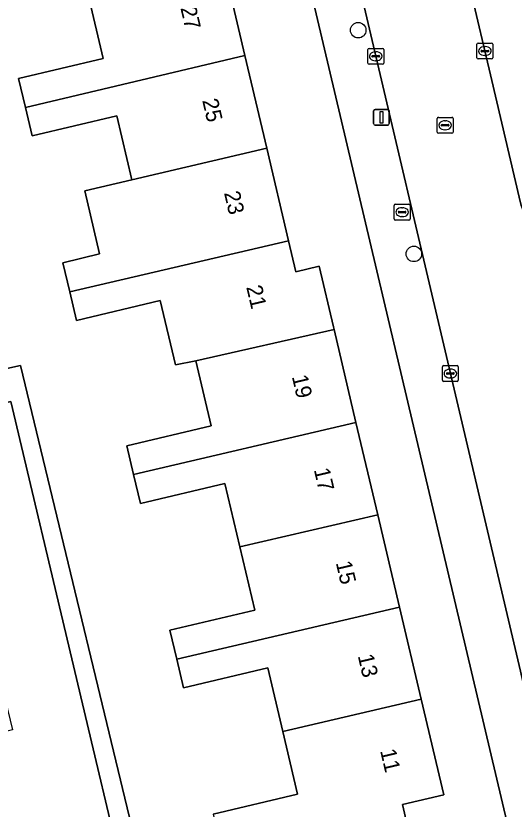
# Model space of a CAD drawing. Extents: x 158031 to 159244, y 380104 to 381214.
# Drawn here: x 158568.4 to 158599.9, y 380796.3 to 380846.4 of the extents above; entities that cross this region are included whole.
import ezdxf

# ---------------------------------------------------------------- set-up
doc = ezdxf.new("R2010")
doc.units = 0
for name, color, linetype in [('IMGEO_Boom', 7, 'Continuous'), ('IMGEO_Brandkraan', 7, 'Continuous'), ('IMGEO_Erf', 7, 'Continuous'), ('IMGEO_Kolk', 7, 'Continuous'), ('IMGEO_Lichtmast', 7, 'Continuous'), ('IMGEO_Pand', 7, 'Continuous'), ('IMGEO_Pand_nummerreeks', 7, 'Continuous'), ('IMGEO_Rijbaan_lokaal_open', 7, 'Continuous'), ('IMGEO_Rioolput', 7, 'Continuous'), ('IMGEO_Voetpad_open', 7, 'Continuous')]:
    doc.layers.add(name, color=color, linetype=linetype)

msp = doc.modelspace()

# ---------------------------------------------------------------- linework, layer by layer
at = {"layer": 'IMGEO_Boom'}
for centre in [(158590.04, 380845.479), (158593.559, 380831.355)]:
    msp.add_circle(centre, 0.489, dxfattribs=at)
at = {"layer": 'IMGEO_Brandkraan'}
for p, q in [((158592.316, 380833.564), (158592.316, 380834.416)), ((158592.391, 380834.49), (158593.243, 380834.49)), ((158592.804, 380834.27), (158592.829, 380834.27)), ((158593.317, 380834.416), (158593.317, 380833.564)), ((158592.575, 380833.984), (158592.575, 380833.996)), ((158593.013, 380833.947), (158592.615, 380833.947)), ((158592.618, 380834.033), (158593.016, 380834.033)), ((158592.827, 380833.71), (158592.802, 380833.71)), ((158593.059, 380833.996), (158593.059, 380833.984)), ((158593.243, 380833.49), (158592.391, 380833.49))]:
    msp.add_line(p, q, dxfattribs=at)
for points in [[(158592.316, 380833.564), (158592.316, 380834.416)], [(158592.391, 380834.49), (158593.243, 380834.49)], [(158593.317, 380834.416), (158593.317, 380833.564)], [(158593.243, 380833.49), (158592.391, 380833.49)]]:
    msp.add_lwpolyline(points, dxfattribs=at)
for centre, radius, start, end in [((158592.393, 380834.414), 0.0765, 91.552, 178.448), ((158592.393, 380834.414), 0.0765, 91.552, 178.448), ((158593.241, 380834.414), 0.0765, 1.552, 88.448), ((158593.241, 380834.414), 0.0765, 1.552, 88.448), ((158592.615, 380833.993), 0.0403, 85.8775, 175.7526), ((158592.612, 380833.983), 0.0366, 178.938, 274.7102), ((158593.016, 380833.99), 0.043, 264.8664, 352.4533), ((158593.02, 380833.995), 0.0386, 1.7309, 96.639), ((158592.393, 380833.566), 0.0765, 181.552, 268.448), ((158592.393, 380833.566), 0.0765, 181.552, 268.448), ((158593.241, 380833.566), 0.0765, 271.552, 358.448), ((158593.241, 380833.566), 0.0765, 271.552, 358.448)]:
    msp.add_arc(centre, radius, start, end, dxfattribs=at)
for centre, major_axis, ratio, start_param, end_param in [((158592.803, 380833.99), (-0.387, 0.002), 0.722429, 4.712389, 7.853982), ((158592.828, 380833.99), (-0.39, 0.002), 0.717154, 1.570796, 4.712389)]:
    msp.add_ellipse(centre, major_axis=major_axis, ratio=ratio, start_param=start_param, end_param=end_param, dxfattribs=at)
at = {"layer": 'IMGEO_Erf'}
for points in [[(158599.515, 380795.166), (158582.927, 380865.443)], [(158581.498, 380849.736), (158582.878, 380843.886), (158584.261, 380838.026), (158585.642, 380832.176), (158586.101, 380830.23), (158587.569, 380830.577), (158588.472, 380826.752), (158588.511, 380826.586), (158589.898, 380820.711), (158591.275, 380814.876), (158592.651, 380809.05), (158594.024, 380803.234), (158595.447, 380797.204), (158592.829, 380796.586), (158593.5, 380793.746)], [(158580.884, 380795.981), (158586.213, 380797.239), (158585.276, 380801.21), (158584.329, 380805.224), (158579.002, 380803.967), (158578.579, 380805.759), (158578.145, 380807.595), (158583.505, 380808.86), (158582.562, 380812.855), (158581.616, 380816.865), (158576.276, 380815.604), (158575.845, 380817.432), (158575.418, 380819.24), (158580.749, 380820.498), (158579.782, 380824.594), (158578.491, 380824.343), (158577.531, 380828.41), (158572.235, 380827.16), (158571.812, 380828.951), (158571.376, 380830.801), (158573.703, 380831.35), (158572.769, 380835.331), (158575.745, 380836.029), (158574.791, 380840.071), (158569.436, 380838.807), (158569.011, 380840.606), (158568.581, 380842.429), (158573.929, 380843.691), (158572.976, 380847.729)], [(158567.641, 380824.075), (158568.7, 380824.316), (158577.028, 380789.836)], [(158575.794, 380789.538), (158568.094, 380822.042), (158558.068, 380819.667), (158559.084, 380815.379), (158564.478, 380816.657), (158564.901, 380814.871), (158565.352, 380812.967), (158559.988, 380811.695), (158560.916, 380807.781), (158561.897, 380803.64), (158567.332, 380804.928), (158567.735, 380803.227), (158568.193, 380801.298), (158562.747, 380800.007), (158563.667, 380796.124)]]:
    msp.add_lwpolyline(points, dxfattribs=at)
at = {"layer": 'IMGEO_Kolk'}
for p, q in [((158590.651, 380843.408), (158590.651, 380844.26)), ((158590.726, 380844.334), (158591.578, 380844.334)), ((158591.652, 380844.26), (158591.652, 380843.408)), ((158597.542, 380843.738), (158597.542, 380844.59)), ((158597.617, 380844.664), (158598.469, 380844.664)), ((158598.03, 380844.444), (158598.055, 380844.444)), ((158598.543, 380844.59), (158598.543, 380843.738)), ((158590.91, 380843.828), (158590.91, 380843.84)), ((158591.348, 380843.791), (158590.95, 380843.791)), ((158590.953, 380843.877), (158591.351, 380843.877)), ((158591.139, 380844.114), (158591.164, 380844.114)), ((158591.394, 380843.84), (158591.394, 380843.828)), ((158597.801, 380844.158), (158597.801, 380844.17)), ((158598.239, 380844.121), (158597.841, 380844.121)), ((158597.844, 380844.207), (158598.242, 380844.207)), ((158598.053, 380843.884), (158598.028, 380843.884)), ((158598.285, 380844.17), (158598.285, 380844.158)), ((158591.578, 380843.334), (158590.726, 380843.334)), ((158591.162, 380843.554), (158591.137, 380843.554)), ((158598.469, 380843.664), (158597.617, 380843.664)), ((158595.365, 380823.377), (158595.365, 380824.229)), ((158595.44, 380824.303), (158596.292, 380824.303)), ((158596.366, 380824.229), (158596.366, 380823.377)), ((158595.624, 380823.797), (158595.624, 380823.809)), ((158596.062, 380823.76), (158595.664, 380823.76)), ((158595.667, 380823.846), (158596.065, 380823.846)), ((158595.853, 380824.083), (158595.878, 380824.083)), ((158596.108, 380823.809), (158596.108, 380823.797)), ((158596.292, 380823.303), (158595.44, 380823.303)), ((158595.876, 380823.523), (158595.851, 380823.523))]:
    msp.add_line(p, q, dxfattribs=at)
for points in [[(158590.651, 380843.408), (158590.651, 380844.26)], [(158590.726, 380844.334), (158591.578, 380844.334)], [(158591.652, 380844.26), (158591.652, 380843.408)], [(158597.542, 380843.738), (158597.542, 380844.59)], [(158597.617, 380844.664), (158598.469, 380844.664)], [(158598.543, 380844.59), (158598.543, 380843.738)], [(158591.578, 380843.334), (158590.726, 380843.334)], [(158598.469, 380843.664), (158597.617, 380843.664)], [(158595.365, 380823.377), (158595.365, 380824.229)], [(158595.44, 380824.303), (158596.292, 380824.303)], [(158596.366, 380824.229), (158596.366, 380823.377)], [(158596.292, 380823.303), (158595.44, 380823.303)]]:
    msp.add_lwpolyline(points, dxfattribs=at)
for centre, radius, start, end in [((158590.728, 380844.258), 0.0765, 91.552, 178.448), ((158590.728, 380844.258), 0.0765, 91.552, 178.448), ((158591.576, 380844.258), 0.0765, 1.552, 88.448), ((158591.576, 380844.258), 0.0765, 1.552, 88.448), ((158597.619, 380844.588), 0.0765, 91.552, 178.448), ((158597.619, 380844.588), 0.0765, 91.552, 178.448), ((158598.467, 380844.588), 0.0765, 1.552, 88.448), ((158598.467, 380844.588), 0.0765, 1.552, 88.448), ((158590.95, 380843.837), 0.0403, 85.8775, 175.7526), ((158590.947, 380843.827), 0.0366, 178.938, 274.7102), ((158591.351, 380843.834), 0.043, 264.8664, 352.4533), ((158591.355, 380843.839), 0.0386, 1.7309, 96.639), ((158597.619, 380843.74), 0.0765, 181.552, 268.448), ((158597.619, 380843.74), 0.0765, 181.552, 268.448), ((158597.841, 380844.167), 0.0403, 85.8775, 175.7526), ((158597.838, 380844.157), 0.0366, 178.938, 274.7102), ((158598.242, 380844.164), 0.043, 264.8664, 352.4533), ((158598.246, 380844.169), 0.0386, 1.7309, 96.639), ((158598.467, 380843.74), 0.0765, 271.552, 358.448), ((158598.467, 380843.74), 0.0765, 271.552, 358.448), ((158590.728, 380843.41), 0.0765, 181.552, 268.448), ((158590.728, 380843.41), 0.0765, 181.552, 268.448), ((158591.576, 380843.41), 0.0765, 271.552, 358.448), ((158591.576, 380843.41), 0.0765, 271.552, 358.448), ((158595.442, 380824.227), 0.0765, 91.552, 178.448), ((158595.442, 380824.227), 0.0765, 91.552, 178.448), ((158596.29, 380824.227), 0.0765, 1.552, 88.448), ((158596.29, 380824.227), 0.0765, 1.552, 88.448), ((158595.664, 380823.806), 0.0403, 85.8775, 175.7526), ((158595.661, 380823.796), 0.0366, 178.938, 274.7102), ((158596.065, 380823.803), 0.043, 264.8664, 352.4533), ((158596.069, 380823.808), 0.0386, 1.7309, 96.639), ((158595.442, 380823.379), 0.0765, 181.552, 268.448), ((158595.442, 380823.379), 0.0765, 181.552, 268.448), ((158596.29, 380823.379), 0.0765, 271.552, 358.448), ((158596.29, 380823.379), 0.0765, 271.552, 358.448)]:
    msp.add_arc(centre, radius, start, end, dxfattribs=at)
for centre, major_axis, ratio, start_param, end_param in [((158598.029, 380844.164), (-0.387, 0.002), 0.722429, 4.712389, 7.853982), ((158598.054, 380844.164), (-0.39, 0.002), 0.717154, 1.570796, 4.712389), ((158591.138, 380843.834), (-0.387, 0.002), 0.722429, 4.712389, 7.853982), ((158591.163, 380843.834), (-0.39, 0.002), 0.717154, 1.570796, 4.712389), ((158595.852, 380823.803), (-0.387, 0.002), 0.722429, 4.712389, 7.853982), ((158595.877, 380823.803), (-0.39, 0.002), 0.717154, 1.570796, 4.712389)]:
    msp.add_ellipse(centre, major_axis=major_axis, ratio=ratio, start_param=start_param, end_param=end_param, dxfattribs=at)
at = {"layer": 'IMGEO_Lichtmast'}
for p, q in [((158591.016, 380839.581), (158591.016, 380840.381)), ((158591.016, 380840.381), (158591.016, 380839.581)), ((158591.116, 380840.481), (158591.906, 380840.481)), ((158591.906, 380840.481), (158591.116, 380840.481)), ((158592.006, 380840.381), (158592.006, 380839.581)), ((158592.006, 380839.581), (158592.006, 380840.381)), ((158591.906, 380839.481), (158591.116, 380839.481)), ((158591.116, 380839.481), (158591.906, 380839.481))]:
    msp.add_line(p, q, dxfattribs=at)
msp.add_lwpolyline([(158591.436, 380840.356), (158591.586, 380840.356), (158591.586, 380839.606), (158591.436, 380839.606), (158591.436, 380840.356)], dxfattribs=at)
for centre, start, end in [((158591.116, 380840.381), 90, 180), ((158591.116, 380840.381), 90, 180), ((158591.906, 380840.381), 0, 90), ((158591.906, 380840.381), 360, 90), ((158591.116, 380839.581), 180, 270), ((158591.116, 380839.581), 180, 270), ((158591.906, 380839.581), 270, 0), ((158591.906, 380839.581), 270, 0)]:
    msp.add_arc(centre, 0.1, start, end, dxfattribs=at)
at = {"layer": 'IMGEO_Pand'}
for points in [[(158569.011, 380840.606), (158582.878, 380843.886), (158581.498, 380849.736), (158572.976, 380847.729), (158573.929, 380843.691), (158568.581, 380842.429)], [(158584.261, 380838.026), (158582.878, 380843.886), (158569.011, 380840.606), (158569.436, 380838.807), (158574.791, 380840.071), (158575.745, 380836.029)], [(158571.812, 380828.951), (158585.642, 380832.176), (158584.261, 380838.026), (158575.745, 380836.029), (158572.769, 380835.331), (158573.703, 380831.35), (158571.376, 380830.801)], [(158586.101, 380830.23), (158585.642, 380832.176), (158571.812, 380828.951), (158572.235, 380827.16), (158577.531, 380828.41), (158578.491, 380824.343), (158579.782, 380824.594), (158588.511, 380826.586), (158588.472, 380826.752), (158587.569, 380830.577)], [(158575.845, 380817.432), (158589.898, 380820.711), (158588.511, 380826.586), (158579.782, 380824.594), (158580.749, 380820.498), (158575.418, 380819.24)], [(158582.562, 380812.855), (158591.275, 380814.876), (158589.898, 380820.711), (158575.845, 380817.432), (158576.276, 380815.604), (158581.616, 380816.865)], [(158578.579, 380805.759), (158592.651, 380809.05), (158591.275, 380814.876), (158582.562, 380812.855), (158583.505, 380808.86), (158578.145, 380807.595)], [(158585.276, 380801.21), (158594.024, 380803.234), (158592.651, 380809.05), (158578.579, 380805.759), (158579.002, 380803.967), (158584.329, 380805.224)], [(158595.447, 380797.204), (158594.024, 380803.234), (158585.276, 380801.21), (158586.213, 380797.239), (158580.884, 380795.981), (158581.329, 380794.095), (158579.837, 380793.743), (158580.541, 380790.762), (158580.558, 380790.689), (158593.5, 380793.746), (158592.829, 380796.586)]]:
    msp.add_lwpolyline(points, close=True, dxfattribs=at)
at = {"layer": 'IMGEO_Rijbaan_lokaal_open'}
msp.add_lwpolyline([(158612.554, 380782.409), (158609.13, 380797.277), (158602.299, 380825.906), (158600.506, 380833.99), (158600.339, 380834.407), (158600.216, 380834.929), (158598.482, 380842.295), (158592.846, 380866.236), (158592.496, 380867.568), (158592.029, 380868.864), (158585.362, 380867.367), (158585.66, 380866.767), (158585.904, 380866.143), (158600.289, 380805.01), (158601.755, 380798.591), (158602.585, 380794.954)], dxfattribs=at)
at = {"layer": 'IMGEO_Rioolput'}
for p, q in [((158595.033, 380839.052), (158595.033, 380839.904)), ((158595.108, 380839.978), (158595.96, 380839.978)), ((158595.521, 380839.758), (158595.546, 380839.758)), ((158596.034, 380839.904), (158596.034, 380839.052)), ((158595.292, 380839.472), (158595.292, 380839.484)), ((158595.73, 380839.435), (158595.332, 380839.435)), ((158595.335, 380839.521), (158595.733, 380839.521)), ((158595.776, 380839.484), (158595.776, 380839.472)), ((158595.96, 380838.978), (158595.108, 380838.978)), ((158595.544, 380839.198), (158595.519, 380839.198))]:
    msp.add_line(p, q, dxfattribs=at)
for points in [[(158595.033, 380839.052), (158595.033, 380839.904)], [(158595.108, 380839.978), (158595.96, 380839.978)], [(158596.034, 380839.904), (158596.034, 380839.052)], [(158595.96, 380838.978), (158595.108, 380838.978)]]:
    msp.add_lwpolyline(points, dxfattribs=at)
for centre, radius, start, end in [((158595.11, 380839.902), 0.0765, 91.552, 178.448), ((158595.11, 380839.902), 0.0765, 91.552, 178.448), ((158595.958, 380839.902), 0.0765, 1.552, 88.448), ((158595.958, 380839.902), 0.0765, 1.552, 88.448), ((158595.332, 380839.481), 0.0403, 85.8775, 175.7526), ((158595.329, 380839.471), 0.0366, 178.938, 274.7102), ((158595.733, 380839.478), 0.043, 264.8664, 352.4533), ((158595.737, 380839.483), 0.0386, 1.7309, 96.639), ((158595.11, 380839.054), 0.0765, 181.552, 268.448), ((158595.11, 380839.054), 0.0765, 181.552, 268.448), ((158595.958, 380839.054), 0.0765, 271.552, 358.448), ((158595.958, 380839.054), 0.0765, 271.552, 358.448)]:
    msp.add_arc(centre, radius, start, end, dxfattribs=at)
for centre, major_axis, ratio, start_param, end_param in [((158595.52, 380839.478), (-0.387, 0.002), 0.722429, 4.712389, 7.853982), ((158595.545, 380839.478), (-0.39, 0.002), 0.717154, 1.570796, 4.712389)]:
    msp.add_ellipse(centre, major_axis=major_axis, ratio=ratio, start_param=start_param, end_param=end_param, dxfattribs=at)
at = {"layer": 'IMGEO_Voetpad_open'}
for points in [[(158602.585, 380794.954), (158601.755, 380798.591), (158600.289, 380805.01), (158585.904, 380866.143), (158585.66, 380866.767), (158585.362, 380867.367), (158580.964, 380866.54), (158581.125, 380866.558), (158581.286, 380866.563), (158581.448, 380866.553), (158581.608, 380866.528), (158581.765, 380866.49), (158581.918, 380866.437), (158582.065, 380866.371), (158582.206, 380866.292), (158582.34, 380866.201), (158582.465, 380866.099), (158582.58, 380865.985), (158582.685, 380865.862), (158582.778, 380865.73), (158582.859, 380865.59), (158582.927, 380865.443), (158599.515, 380795.166)], [(158592.846, 380866.236), (158598.482, 380842.295), (158600.216, 380834.929), (158600.339, 380834.407), (158600.506, 380833.99), (158600.636, 380833.751), (158600.786, 380833.525), (158600.957, 380833.313), (158601.145, 380833.117), (158601.35, 380832.938), (158601.539, 380832.8), (158602.423, 380832.171), (158602.45, 380832.149), (158602.631, 380831.98), (158602.797, 380831.795), (158602.945, 380831.597), (158603.075, 380831.386), (158603.186, 380831.164), (158603.276, 380830.933), (158606.935, 380815.371), (158608.844, 380807.251), (158611.089, 380797.703), (158609.13, 380797.277), (158612.554, 380782.409)]]:
    msp.add_lwpolyline(points, dxfattribs=at)
msp.add_lwpolyline([(158575.794, 380789.538), (158577.028, 380789.836), (158568.7, 380824.316), (158567.641, 380824.075), (158561.065, 380852.917), (158559.623, 380859.031), (158562.638, 380859.742), (158562.085, 380862.085), (158554.603, 380860.32), (158555.166, 380857.934), (158558.183, 380858.646), (158559.622, 380852.545), (158566.537, 380823.228), (158556.446, 380820.79), (158552.507, 380819.856), (158547.641, 380818.703), (158544.228, 380817.894), (158544.566, 380816.468), (158549.386, 380817.61), (158554.252, 380818.763), (158558.068, 380819.667), (158568.094, 380822.042)], close=True, dxfattribs=at)

# ---------------------------------------------------------------- texts
at = {"layer": 'IMGEO_Pand_nummerreeks'}
for s, rotation, p in [('27', 283.2796, (158578.801, 380846.882)), ('25', 283.2796, (158580.178, 380841.046)), ('23', 283.2796, (158581.555, 380835.21)), ('21', 283.281, (158582.96, 380829.263)), ('19', 283.2819, (158585.843, 380823.61)), ('17', 283.2819, (158587.231, 380817.734)), ('15', 283.2819, (158588.618, 380811.858)), ('13', 283.2819, (158590.005, 380805.981)), ('11', 283.281, (158591.419, 380799.993))]:
    msp.add_text(s, height=1, rotation=rotation, dxfattribs=at).set_placement(p)

doc.saveas('drawing.dxf')
